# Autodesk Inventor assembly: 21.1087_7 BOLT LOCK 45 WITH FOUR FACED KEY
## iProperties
Created: 2007-03
Part Number: 21.1087_7 BOLT LOCK 45 WITH FOUR FACED KEY
Document SubType Name: Assembly
Designer: Andy Moles
Author: Andy Moles
